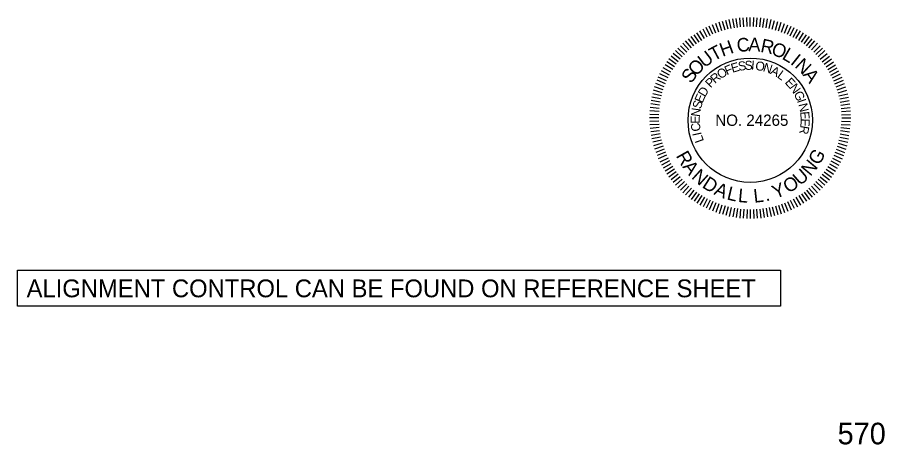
# Model space of a CAD drawing. Extents: x 1964850 to 1967424, y 1116563 to 1122204.
# Drawn here: x 1967080.5 to 1967421.9, y 1120475.5 to 1120643.6 of the extents above; entities that cross this region are included whole.
import ezdxf

# ---------------------------------------------------------------- set-up
doc = ezdxf.new("R2010")
doc.units = 0
for name, color, linetype in [('RD_DDB_Profile_Elev', 7, 'Continuous'), ('RD_Sketch1', 7, 'Continuous'), ('RD_TX_PEShield', 7, 'Continuous')]:
    doc.layers.add(name, color=color, linetype=linetype)

msp = doc.modelspace()

# ---------------------------------------------------------------- linework, layer by layer
at = {"layer": 'RD_Sketch1'}
msp.add_lwpolyline([(1967080.47, 1120544.18), (1967380.89, 1120544.18), (1967380.89, 1120529.92), (1967080.47, 1120529.92)], close=True, dxfattribs=at)
at = {"layer": 'RD_TX_PEShield'}
for p, q in [((1967369.01, 1120640.07), (1967369.01, 1120643.63)), ((1967369.01, 1120640.07), (1967369.01, 1120643.63)), ((1967354.35, 1120636.95), (1967352.9, 1120640.2)), ((1967354.35, 1120636.95), (1967352.9, 1120640.2)), ((1967355.53, 1120637.4), (1967354.19, 1120640.7)), ((1967355.53, 1120637.4), (1967354.19, 1120640.7)), ((1967356.7, 1120637.85), (1967355.48, 1120641.19)), ((1967356.7, 1120637.85), (1967355.48, 1120641.19)), ((1967357.87, 1120638.3), (1967356.77, 1120641.69)), ((1967357.87, 1120638.3), (1967356.77, 1120641.69)), ((1967359.09, 1120638.63), (1967358.11, 1120642.04)), ((1967359.09, 1120638.63), (1967358.11, 1120642.04)), ((1967360.3, 1120638.95), (1967359.44, 1120642.4)), ((1967360.3, 1120638.95), (1967359.44, 1120642.4)), ((1967361.52, 1120639.28), (1967360.78, 1120642.76)), ((1967361.52, 1120639.28), (1967360.78, 1120642.76)), ((1967362.76, 1120639.47), (1967362.14, 1120642.98)), ((1967362.76, 1120639.47), (1967362.14, 1120642.98)), ((1967364, 1120639.67), (1967363.51, 1120643.19)), ((1967364, 1120639.67), (1967363.51, 1120643.19)), ((1967365.24, 1120639.87), (1967364.87, 1120643.41)), ((1967365.24, 1120639.87), (1967364.87, 1120643.41)), ((1967366.5, 1120639.93), (1967366.25, 1120643.48)), ((1967366.5, 1120639.93), (1967366.25, 1120643.48)), ((1967367.76, 1120640), (1967367.63, 1120643.55)), ((1967367.76, 1120640), (1967367.63, 1120643.55)), ((1967370.27, 1120640), (1967370.39, 1120643.55)), ((1967370.27, 1120640), (1967370.39, 1120643.55)), ((1967371.52, 1120639.93), (1967371.77, 1120643.48)), ((1967371.52, 1120639.93), (1967371.77, 1120643.48)), ((1967372.78, 1120639.87), (1967373.15, 1120643.41)), ((1967372.78, 1120639.87), (1967373.15, 1120643.41)), ((1967374.02, 1120639.67), (1967374.52, 1120643.19)), ((1967374.02, 1120639.67), (1967374.52, 1120643.19)), ((1967375.26, 1120639.47), (1967375.88, 1120642.98)), ((1967375.26, 1120639.47), (1967375.88, 1120642.98)), ((1967376.51, 1120639.28), (1967377.25, 1120642.76)), ((1967376.51, 1120639.28), (1967377.25, 1120642.76)), ((1967376.51, 1120639.28), (1967377.25, 1120642.76)), ((1967377.72, 1120638.95), (1967378.58, 1120642.4)), ((1967377.72, 1120638.95), (1967378.58, 1120642.4)), ((1967377.72, 1120638.95), (1967378.58, 1120642.4)), ((1967378.93, 1120638.63), (1967379.91, 1120642.04)), ((1967378.93, 1120638.63), (1967379.91, 1120642.04)), ((1967378.93, 1120638.63), (1967379.91, 1120642.04)), ((1967380.15, 1120638.3), (1967381.25, 1120641.69)), ((1967380.15, 1120638.3), (1967381.25, 1120641.69)), ((1967380.15, 1120638.3), (1967381.25, 1120641.69)), ((1967381.32, 1120637.85), (1967382.54, 1120641.19)), ((1967381.32, 1120637.85), (1967382.54, 1120641.19)), ((1967381.32, 1120637.85), (1967382.54, 1120641.19)), ((1967382.5, 1120637.4), (1967383.83, 1120640.7)), ((1967382.5, 1120637.4), (1967383.83, 1120640.7)), ((1967382.5, 1120637.4), (1967383.83, 1120640.7)), ((1967383.67, 1120636.95), (1967385.12, 1120640.2)), ((1967383.67, 1120636.95), (1967385.12, 1120640.2)), ((1967383.67, 1120636.95), (1967385.12, 1120640.2)), ((1967348.88, 1120633.87), (1967346.89, 1120636.81)), ((1967348.88, 1120633.87), (1967346.89, 1120636.81)), ((1967349.93, 1120634.55), (1967348.05, 1120637.57)), ((1967349.93, 1120634.55), (1967348.05, 1120637.57)), ((1967350.99, 1120635.24), (1967349.21, 1120638.32)), ((1967350.99, 1120635.24), (1967349.21, 1120638.32)), ((1967352.11, 1120635.81), (1967350.44, 1120638.95)), ((1967352.11, 1120635.81), (1967350.44, 1120638.95)), ((1967353.23, 1120636.38), (1967351.67, 1120639.57)), ((1967353.23, 1120636.38), (1967351.67, 1120639.57)), ((1967384.79, 1120636.38), (1967386.35, 1120639.57)), ((1967384.79, 1120636.38), (1967386.35, 1120639.57)), ((1967384.79, 1120636.38), (1967386.35, 1120639.57)), ((1967385.91, 1120635.81), (1967387.58, 1120638.95)), ((1967385.91, 1120635.81), (1967387.58, 1120638.95)), ((1967385.91, 1120635.81), (1967387.58, 1120638.95)), ((1967387.03, 1120635.24), (1967388.81, 1120638.32)), ((1967387.03, 1120635.24), (1967388.81, 1120638.32)), ((1967387.03, 1120635.24), (1967388.81, 1120638.32)), ((1967388.09, 1120634.55), (1967389.97, 1120637.57)), ((1967388.09, 1120634.55), (1967389.97, 1120637.57)), ((1967388.09, 1120634.55), (1967389.97, 1120637.57)), ((1967389.14, 1120633.87), (1967391.13, 1120636.81)), ((1967389.14, 1120633.87), (1967391.13, 1120636.81)), ((1967389.14, 1120633.87), (1967391.13, 1120636.81)), ((1967344.89, 1120630.81), (1967342.51, 1120633.45)), ((1967344.89, 1120630.81), (1967342.51, 1120633.45)), ((1967345.87, 1120631.6), (1967343.59, 1120634.32)), ((1967345.87, 1120631.6), (1967343.59, 1120634.32)), ((1967346.85, 1120632.39), (1967344.66, 1120635.19)), ((1967346.85, 1120632.39), (1967344.66, 1120635.19)), ((1967347.82, 1120633.18), (1967345.73, 1120636.06)), ((1967347.82, 1120633.18), (1967345.73, 1120636.06)), ((1967390.2, 1120633.18), (1967392.29, 1120636.06)), ((1967390.2, 1120633.18), (1967392.29, 1120636.06)), ((1967390.2, 1120633.18), (1967392.29, 1120636.06)), ((1967391.18, 1120632.39), (1967393.37, 1120635.19)), ((1967391.18, 1120632.39), (1967393.37, 1120635.19)), ((1967391.18, 1120632.39), (1967393.37, 1120635.19)), ((1967392.15, 1120631.6), (1967394.44, 1120634.32)), ((1967392.15, 1120631.6), (1967394.44, 1120634.32)), ((1967392.15, 1120631.6), (1967394.44, 1120634.32)), ((1967393.13, 1120630.81), (1967395.51, 1120633.45)), ((1967393.13, 1120630.81), (1967395.51, 1120633.45)), ((1967393.13, 1120630.81), (1967395.51, 1120633.45)), ((1967342.22, 1120628.14), (1967339.58, 1120630.52)), ((1967342.22, 1120628.14), (1967339.58, 1120630.52)), ((1967343.11, 1120629.03), (1967340.56, 1120631.5)), ((1967343.11, 1120629.03), (1967340.56, 1120631.5)), ((1967344, 1120629.92), (1967341.53, 1120632.48)), ((1967344, 1120629.92), (1967341.53, 1120632.48)), ((1967394.02, 1120629.92), (1967396.49, 1120632.48)), ((1967394.02, 1120629.92), (1967396.49, 1120632.48)), ((1967394.02, 1120629.92), (1967396.49, 1120632.48)), ((1967394.91, 1120629.03), (1967397.47, 1120631.5)), ((1967394.91, 1120629.03), (1967397.47, 1120631.5)), ((1967394.91, 1120629.03), (1967397.47, 1120631.5)), ((1967395.8, 1120628.14), (1967398.44, 1120630.52)), ((1967395.8, 1120628.14), (1967398.44, 1120630.52)), ((1967395.8, 1120628.14), (1967398.44, 1120630.52)), ((1967339.85, 1120625.21), (1967336.97, 1120627.3)), ((1967339.85, 1120625.21), (1967336.97, 1120627.3)), ((1967340.64, 1120626.18), (1967337.84, 1120628.37)), ((1967340.64, 1120626.18), (1967337.84, 1120628.37)), ((1967341.43, 1120627.16), (1967338.71, 1120629.45)), ((1967341.43, 1120627.16), (1967338.71, 1120629.45)), ((1967396.59, 1120627.16), (1967399.31, 1120629.45)), ((1967396.59, 1120627.16), (1967399.31, 1120629.45)), ((1967396.59, 1120627.16), (1967399.31, 1120629.45)), ((1967397.38, 1120626.18), (1967400.18, 1120628.37)), ((1967397.38, 1120626.18), (1967400.18, 1120628.37)), ((1967397.38, 1120626.18), (1967400.18, 1120628.37)), ((1967398.17, 1120625.21), (1967401.05, 1120627.3)), ((1967398.17, 1120625.21), (1967401.05, 1120627.3)), ((1967398.17, 1120625.21), (1967401.05, 1120627.3)), ((1967337.8, 1120622.04), (1967334.71, 1120623.82)), ((1967337.8, 1120622.04), (1967334.71, 1120623.82)), ((1967338.48, 1120623.1), (1967335.47, 1120624.98)), ((1967338.48, 1120623.1), (1967335.47, 1120624.98)), ((1967339.17, 1120624.15), (1967336.22, 1120626.14)), ((1967339.17, 1120624.15), (1967336.22, 1120626.14)), ((1967398.86, 1120624.15), (1967401.81, 1120626.14)), ((1967398.86, 1120624.15), (1967401.81, 1120626.14)), ((1967398.86, 1120624.15), (1967401.81, 1120626.14)), ((1967399.54, 1120623.1), (1967402.56, 1120624.98)), ((1967399.54, 1120623.1), (1967402.56, 1120624.98)), ((1967399.54, 1120623.1), (1967402.56, 1120624.98)), ((1967400.23, 1120622.04), (1967403.31, 1120623.82)), ((1967400.23, 1120622.04), (1967403.31, 1120623.82)), ((1967400.23, 1120622.04), (1967403.31, 1120623.82)), ((1967336.08, 1120618.68), (1967332.83, 1120620.13)), ((1967336.08, 1120618.68), (1967332.83, 1120620.13)), ((1967336.65, 1120619.8), (1967333.46, 1120621.36)), ((1967336.65, 1120619.8), (1967333.46, 1120621.36)), ((1967337.22, 1120620.92), (1967334.09, 1120622.59)), ((1967337.22, 1120620.92), (1967334.09, 1120622.59)), ((1967400.8, 1120620.92), (1967403.94, 1120622.59)), ((1967400.8, 1120620.92), (1967403.94, 1120622.59)), ((1967400.8, 1120620.92), (1967403.94, 1120622.59)), ((1967401.37, 1120619.8), (1967404.57, 1120621.36)), ((1967401.37, 1120619.8), (1967404.57, 1120621.36)), ((1967401.37, 1120619.8), (1967404.57, 1120621.36)), ((1967401.94, 1120618.68), (1967405.19, 1120620.13)), ((1967401.94, 1120618.68), (1967405.19, 1120620.13)), ((1967401.94, 1120618.68), (1967405.19, 1120620.13)), ((1967335.18, 1120616.33), (1967331.84, 1120617.55)), ((1967335.18, 1120616.33), (1967331.84, 1120617.55)), ((1967335.63, 1120617.51), (1967332.34, 1120618.84)), ((1967335.63, 1120617.51), (1967332.34, 1120618.84)), ((1967402.39, 1120617.51), (1967405.69, 1120618.84)), ((1967402.39, 1120617.51), (1967405.69, 1120618.84)), ((1967402.39, 1120617.51), (1967405.69, 1120618.84)), ((1967402.84, 1120616.33), (1967406.18, 1120617.55)), ((1967402.84, 1120616.33), (1967406.18, 1120617.55)), ((1967402.84, 1120616.33), (1967406.18, 1120617.55)), ((1967334.08, 1120612.73), (1967330.63, 1120613.59)), ((1967334.08, 1120612.73), (1967330.63, 1120613.59)), ((1967334.41, 1120613.94), (1967330.99, 1120614.92)), ((1967334.41, 1120613.94), (1967330.99, 1120614.92)), ((1967334.73, 1120615.16), (1967331.35, 1120616.26)), ((1967334.73, 1120615.16), (1967331.35, 1120616.26)), ((1967403.29, 1120615.16), (1967406.68, 1120616.26)), ((1967403.29, 1120615.16), (1967406.68, 1120616.26)), ((1967403.29, 1120615.16), (1967406.68, 1120616.26)), ((1967403.62, 1120613.94), (1967407.04, 1120614.92)), ((1967403.62, 1120613.94), (1967407.04, 1120614.92)), ((1967403.62, 1120613.94), (1967407.04, 1120614.92)), ((1967403.94, 1120612.73), (1967407.39, 1120613.59)), ((1967403.94, 1120612.73), (1967407.39, 1120613.59)), ((1967403.94, 1120612.73), (1967407.39, 1120613.59)), ((1967333.36, 1120609.03), (1967329.84, 1120609.53)), ((1967333.36, 1120609.03), (1967329.84, 1120609.53)), ((1967333.56, 1120610.27), (1967330.06, 1120610.89)), ((1967333.56, 1120610.27), (1967330.06, 1120610.89)), ((1967333.75, 1120611.51), (1967330.27, 1120612.25)), ((1967333.75, 1120611.51), (1967330.27, 1120612.25)), ((1967404.27, 1120611.51), (1967407.75, 1120612.25)), ((1967404.27, 1120611.51), (1967407.75, 1120612.25)), ((1967404.27, 1120611.51), (1967407.75, 1120612.25)), ((1967404.47, 1120610.27), (1967407.97, 1120610.89)), ((1967404.47, 1120610.27), (1967407.97, 1120610.89)), ((1967404.47, 1120610.27), (1967407.97, 1120610.89)), ((1967404.66, 1120609.03), (1967408.18, 1120609.53)), ((1967404.66, 1120609.03), (1967408.18, 1120609.53)), ((1967404.66, 1120609.03), (1967408.18, 1120609.53)), ((1967333.1, 1120606.53), (1967329.55, 1120606.78)), ((1967333.1, 1120606.53), (1967329.55, 1120606.78)), ((1967333.16, 1120607.79), (1967329.62, 1120608.16)), ((1967333.16, 1120607.79), (1967329.62, 1120608.16)), ((1967404.86, 1120607.79), (1967408.4, 1120608.16)), ((1967404.86, 1120607.79), (1967408.4, 1120608.16)), ((1967404.86, 1120607.79), (1967408.4, 1120608.16)), ((1967404.93, 1120606.53), (1967408.47, 1120606.78)), ((1967404.93, 1120606.53), (1967408.47, 1120606.78)), ((1967404.93, 1120606.53), (1967408.47, 1120606.78)), ((1967332.97, 1120604.02), (1967329.41, 1120604.02)), ((1967332.97, 1120604.02), (1967329.41, 1120604.02)), ((1967333.03, 1120605.28), (1967329.48, 1120605.4)), ((1967333.03, 1120605.28), (1967329.48, 1120605.4)), ((1967333.03, 1120602.76), (1967329.48, 1120602.64)), ((1967333.03, 1120602.76), (1967329.48, 1120602.64)), ((1967404.92, 1120602.77), (1967408.47, 1120602.64)), ((1967404.92, 1120602.77), (1967408.47, 1120602.64)), ((1967404.99, 1120605.28), (1967408.54, 1120605.4)), ((1967404.99, 1120605.28), (1967408.54, 1120605.4)), ((1967404.99, 1120605.28), (1967408.54, 1120605.4)), ((1967405.06, 1120604.02), (1967408.62, 1120604.02)), ((1967405.06, 1120604.02), (1967408.62, 1120604.02)), ((1967405.06, 1120604.02), (1967408.62, 1120604.02)), ((1967333.1, 1120601.51), (1967329.55, 1120601.26)), ((1967333.1, 1120601.51), (1967329.55, 1120601.26)), ((1967333.16, 1120600.25), (1967329.62, 1120599.88)), ((1967333.16, 1120600.25), (1967329.62, 1120599.88)), ((1967404.66, 1120600.27), (1967408.18, 1120599.9)), ((1967404.66, 1120600.27), (1967408.18, 1120599.9)), ((1967404.79, 1120601.52), (1967408.33, 1120601.27)), ((1967404.79, 1120601.52), (1967408.33, 1120601.27)), ((1967333.36, 1120599.01), (1967329.84, 1120598.52)), ((1967333.36, 1120599.01), (1967329.84, 1120598.52)), ((1967333.56, 1120597.77), (1967330.06, 1120597.15)), ((1967333.56, 1120597.77), (1967330.06, 1120597.15)), ((1967333.75, 1120596.53), (1967330.27, 1120595.79)), ((1967333.75, 1120596.53), (1967330.27, 1120595.79)), ((1967404.27, 1120596.53), (1967407.75, 1120595.79)), ((1967404.27, 1120596.53), (1967407.75, 1120595.79)), ((1967404.4, 1120597.78), (1967407.9, 1120597.16)), ((1967404.4, 1120597.78), (1967407.9, 1120597.16)), ((1967404.53, 1120599.03), (1967408.04, 1120598.54)), ((1967404.53, 1120599.03), (1967408.04, 1120598.54)), ((1967334.08, 1120595.31), (1967330.63, 1120594.45)), ((1967334.08, 1120595.31), (1967330.63, 1120594.45)), ((1967334.41, 1120594.1), (1967330.99, 1120593.12)), ((1967334.41, 1120594.1), (1967330.99, 1120593.12)), ((1967334.73, 1120592.88), (1967331.35, 1120591.78)), ((1967403.29, 1120592.88), (1967406.68, 1120591.78)), ((1967403.29, 1120592.88), (1967406.68, 1120591.78)), ((1967403.62, 1120594.1), (1967407.04, 1120593.12)), ((1967403.62, 1120594.1), (1967407.04, 1120593.12)), ((1967403.94, 1120595.31), (1967407.39, 1120594.45)), ((1967403.94, 1120595.31), (1967407.39, 1120594.45)), ((1967335.18, 1120591.71), (1967331.84, 1120590.49)), ((1967335.18, 1120591.71), (1967331.84, 1120590.49)), ((1967335.63, 1120590.53), (1967332.34, 1120589.2)), ((1967335.63, 1120590.53), (1967332.34, 1120589.2)), ((1967336.08, 1120589.36), (1967332.83, 1120587.91)), ((1967336.08, 1120589.36), (1967332.83, 1120587.91)), ((1967401.94, 1120589.36), (1967405.19, 1120587.91)), ((1967401.94, 1120589.36), (1967405.19, 1120587.91)), ((1967402.39, 1120590.53), (1967405.69, 1120589.2)), ((1967402.39, 1120590.53), (1967405.69, 1120589.2)), ((1967402.84, 1120591.71), (1967406.18, 1120590.49)), ((1967402.84, 1120591.71), (1967406.18, 1120590.49)), ((1967336.65, 1120588.24), (1967333.46, 1120586.68)), ((1967336.65, 1120588.24), (1967333.46, 1120586.68)), ((1967337.22, 1120587.12), (1967334.09, 1120585.45)), ((1967337.22, 1120587.12), (1967334.09, 1120585.45)), ((1967337.8, 1120586), (1967334.71, 1120584.22)), ((1967337.8, 1120586), (1967334.71, 1120584.22)), ((1967400.23, 1120586), (1967403.31, 1120584.22)), ((1967400.23, 1120586), (1967403.31, 1120584.22)), ((1967400.8, 1120587.12), (1967403.94, 1120585.45)), ((1967400.8, 1120587.12), (1967403.94, 1120585.45)), ((1967401.37, 1120588.24), (1967404.57, 1120586.68)), ((1967401.37, 1120588.24), (1967404.57, 1120586.68)), ((1967338.48, 1120584.94), (1967335.47, 1120583.06)), ((1967338.48, 1120584.94), (1967335.47, 1120583.06)), ((1967339.17, 1120583.89), (1967336.22, 1120581.9)), ((1967339.17, 1120583.89), (1967336.22, 1120581.9)), ((1967339.85, 1120582.83), (1967336.97, 1120580.74)), ((1967339.85, 1120582.83), (1967336.97, 1120580.74)), ((1967398.17, 1120582.83), (1967401.05, 1120580.74)), ((1967398.17, 1120582.83), (1967401.05, 1120580.74)), ((1967398.86, 1120583.89), (1967401.81, 1120581.9)), ((1967398.86, 1120583.89), (1967401.81, 1120581.9)), ((1967399.54, 1120584.94), (1967402.56, 1120583.06)), ((1967399.54, 1120584.94), (1967402.56, 1120583.06)), ((1967340.64, 1120581.86), (1967337.84, 1120579.67)), ((1967340.64, 1120581.86), (1967337.84, 1120579.67)), ((1967341.43, 1120580.88), (1967338.71, 1120578.59)), ((1967341.43, 1120580.88), (1967338.71, 1120578.59)), ((1967342.22, 1120579.9), (1967339.58, 1120577.52)), ((1967342.22, 1120579.9), (1967339.58, 1120577.52)), ((1967343.11, 1120579.01), (1967340.56, 1120576.54)), ((1967343.11, 1120579.01), (1967340.56, 1120576.54)), ((1967394.91, 1120579.01), (1967397.47, 1120576.54)), ((1967394.91, 1120579.01), (1967397.47, 1120576.54)), ((1967395.8, 1120579.9), (1967398.44, 1120577.52)), ((1967395.8, 1120579.9), (1967398.44, 1120577.52)), ((1967396.59, 1120580.88), (1967399.31, 1120578.59)), ((1967396.59, 1120580.88), (1967399.31, 1120578.59)), ((1967397.38, 1120581.86), (1967400.18, 1120579.67)), ((1967397.38, 1120581.86), (1967400.18, 1120579.67)), ((1967344, 1120578.12), (1967341.53, 1120575.57)), ((1967344, 1120578.12), (1967341.53, 1120575.57)), ((1967344.89, 1120577.23), (1967342.51, 1120574.59)), ((1967344.89, 1120577.23), (1967342.51, 1120574.59)), ((1967345.87, 1120576.44), (1967343.59, 1120573.72)), ((1967345.87, 1120576.44), (1967343.59, 1120573.72)), ((1967346.85, 1120575.65), (1967344.66, 1120572.85)), ((1967346.85, 1120575.65), (1967344.66, 1120572.85)), ((1967391.18, 1120575.65), (1967393.37, 1120572.85)), ((1967391.18, 1120575.65), (1967393.37, 1120572.85)), ((1967392.15, 1120576.44), (1967394.44, 1120573.72)), ((1967392.15, 1120576.44), (1967394.44, 1120573.72)), ((1967393.13, 1120577.23), (1967395.51, 1120574.59)), ((1967394.02, 1120578.12), (1967396.49, 1120575.57)), ((1967394.02, 1120578.12), (1967396.49, 1120575.57)), ((1967347.82, 1120574.86), (1967345.73, 1120571.98)), ((1967347.82, 1120574.86), (1967345.73, 1120571.98)), ((1967348.88, 1120574.17), (1967346.89, 1120571.23)), ((1967348.88, 1120574.17), (1967346.89, 1120571.23)), ((1967349.93, 1120573.49), (1967348.05, 1120570.47)), ((1967349.93, 1120573.49), (1967348.05, 1120570.47)), ((1967350.99, 1120572.8), (1967349.21, 1120569.72)), ((1967350.99, 1120572.8), (1967349.21, 1120569.72)), ((1967352.11, 1120572.23), (1967350.44, 1120569.09)), ((1967352.11, 1120572.23), (1967350.44, 1120569.09)), ((1967385.91, 1120572.23), (1967387.58, 1120569.09)), ((1967385.91, 1120572.23), (1967387.58, 1120569.09)), ((1967387.03, 1120572.8), (1967388.81, 1120569.72)), ((1967387.03, 1120572.8), (1967388.81, 1120569.72)), ((1967388.09, 1120573.49), (1967389.97, 1120570.47)), ((1967388.09, 1120573.49), (1967389.97, 1120570.47)), ((1967389.14, 1120574.17), (1967391.13, 1120571.23)), ((1967389.14, 1120574.17), (1967391.13, 1120571.23)), ((1967390.2, 1120574.86), (1967392.29, 1120571.98)), ((1967390.2, 1120574.86), (1967392.29, 1120571.98)), ((1967353.23, 1120571.66), (1967351.67, 1120568.47)), ((1967353.23, 1120571.66), (1967351.67, 1120568.47)), ((1967354.35, 1120571.09), (1967352.9, 1120567.84)), ((1967354.35, 1120571.09), (1967352.9, 1120567.84)), ((1967355.53, 1120570.64), (1967354.19, 1120567.34)), ((1967355.53, 1120570.64), (1967354.19, 1120567.34)), ((1967356.7, 1120570.19), (1967355.48, 1120566.85)), ((1967356.7, 1120570.19), (1967355.48, 1120566.85)), ((1967357.87, 1120569.74), (1967356.77, 1120566.35)), ((1967357.87, 1120569.74), (1967356.77, 1120566.35)), ((1967359.09, 1120569.41), (1967358.11, 1120566)), ((1967359.09, 1120569.41), (1967358.11, 1120566)), ((1967360.3, 1120569.09), (1967359.44, 1120565.64)), ((1967360.3, 1120569.09), (1967359.44, 1120565.64)), ((1967361.52, 1120568.76), (1967360.78, 1120565.28)), ((1967361.52, 1120568.76), (1967360.78, 1120565.28)), ((1967362.76, 1120568.57), (1967362.14, 1120565.06)), ((1967362.76, 1120568.57), (1967362.14, 1120565.06)), ((1967375.26, 1120568.57), (1967375.88, 1120565.06)), ((1967375.26, 1120568.57), (1967375.88, 1120565.06)), ((1967376.51, 1120568.76), (1967377.25, 1120565.28)), ((1967376.51, 1120568.76), (1967377.25, 1120565.28)), ((1967377.72, 1120569.09), (1967378.58, 1120565.64)), ((1967377.72, 1120569.09), (1967378.58, 1120565.64)), ((1967378.93, 1120569.41), (1967379.91, 1120566)), ((1967378.93, 1120569.41), (1967379.91, 1120566)), ((1967380.15, 1120569.74), (1967381.25, 1120566.35)), ((1967380.15, 1120569.74), (1967381.25, 1120566.35)), ((1967381.32, 1120570.19), (1967382.54, 1120566.85)), ((1967381.32, 1120570.19), (1967382.54, 1120566.85)), ((1967382.5, 1120570.64), (1967383.83, 1120567.34)), ((1967382.5, 1120570.64), (1967383.83, 1120567.34)), ((1967383.67, 1120571.09), (1967385.12, 1120567.84)), ((1967383.67, 1120571.09), (1967385.12, 1120567.84)), ((1967384.79, 1120571.66), (1967386.35, 1120568.47)), ((1967384.79, 1120571.66), (1967386.35, 1120568.47)), ((1967364, 1120568.37), (1967363.51, 1120564.85)), ((1967364, 1120568.37), (1967363.51, 1120564.85)), ((1967365.24, 1120568.17), (1967364.87, 1120564.63)), ((1967365.24, 1120568.17), (1967364.87, 1120564.63)), ((1967366.5, 1120568.11), (1967366.25, 1120564.56)), ((1967366.5, 1120568.11), (1967366.25, 1120564.56)), ((1967367.76, 1120568.04), (1967367.63, 1120564.49)), ((1967367.76, 1120568.04), (1967367.63, 1120564.49)), ((1967369.01, 1120567.98), (1967369.01, 1120564.42)), ((1967369.01, 1120567.98), (1967369.01, 1120564.42)), ((1967370.27, 1120568.04), (1967370.39, 1120564.49)), ((1967370.27, 1120568.04), (1967370.39, 1120564.49)), ((1967371.52, 1120568.11), (1967371.77, 1120564.56)), ((1967371.52, 1120568.11), (1967371.77, 1120564.56)), ((1967372.78, 1120568.17), (1967373.15, 1120564.63)), ((1967372.78, 1120568.17), (1967373.15, 1120564.63)), ((1967374.02, 1120568.37), (1967374.52, 1120564.85)), ((1967374.02, 1120568.37), (1967374.52, 1120564.85))]:
    msp.add_line(p, q, dxfattribs=at)
msp.add_circle((1967369.01, 1120603.14), 24.48, dxfattribs=at)

# ---------------------------------------------------------------- texts
at = {"layer": 'RD_DDB_Profile_Elev'}
msp.add_text('570', height=8.5, dxfattribs=at).set_placement((1967403.42, 1120475.58))
at = {"layer": 'RD_Sketch1'}
msp.add_text('ALIGNMENT CONTROL CAN BE FOUND ON REFERENCE SHEET', height=7, dxfattribs=at).set_placement((1967084.12, 1120533.46))
at = {"layer": 'RD_TX_PEShield'}
for s, height, rotation, p in [('H', 5.34, 19.9102, (1967358.11, 1120628.06)), ('C', 5.34, 6.8832, (1967364.01, 1120629.88)), ('A', 5.34, 357.9448, (1967368.22, 1120630.33)), ('R', 5.34, 348.267, (1967372.8, 1120630.08)), ('O', 5.34, 339.3286, (1967376.94, 1120629.16)), ('U', 5.34, 37.7726, (1967350.99, 1120623.52)), ('T', 5.34, 28.0947, (1967354.67, 1120626.26)), ('L', 5.34, 329.6507, (1967381.2, 1120627.46)), ('O', 5.34, 47.4504, (1967347.82, 1120620.2)), ('S', 3.56, 1.79, (1967366.86, 1120622.93)), ('I', 3.56, 354.889, (1967369.26, 1120623.05)), ('I', 5.34, 321.4663, (1967384.54, 1120625.48)), ('N', 5.34, 317.0007, (1967386.23, 1120624.2)), ('S', 5.34, 54.9027, (1967345.79, 1120617.31)), ('O', 3.56, 31.7869, (1967357.26, 1120619.21)), ('F', 3.56, 23.0853, (1967359.82, 1120620.8)), ('E', 3.56, 16.1843, (1967362.01, 1120621.78)), ('S', 3.56, 8.6909, (1967364.5, 1120622.53)), ('O', 3.56, 350.4045, (1967370.81, 1120622.97)), ('N', 3.56, 341.7029, (1967373.79, 1120622.47)), ('A', 3.56, 333.0013, (1967376.66, 1120621.52)), ('P', 3.56, 46.7912, (1967353.5, 1120615.62)), ('R', 3.56, 39.8902, (1967355.11, 1120617.39)), ('L', 3.56, 324.2997, (1967379.35, 1120620.15)), ('E', 3.56, 313.2251, (1967382.43, 1120617.85)), ('A', 5.34, 307.3229, (1967389.53, 1120621)), ('N', 3.56, 305.7317, (1967384.23, 1120615.98)), ('E', 3.56, 66.5674, (1967350.19, 1120609.63)), ('D', 3.56, 59.074, (1967351.2, 1120612.03)), ('G', 3.56, 297.0301, (1967386, 1120613.53)), ('S', 3.56, 73.4683, (1967349.55, 1120607.32)), ('I', 3.56, 288.3285, (1967387.37, 1120610.84)), ('N', 3.56, 283.8441, (1967387.92, 1120609.38)), ('N', 3.56, 82.17, (1967349.14, 1120604.33)), ('E', 3.56, 275.1424, (1967388.64, 1120606.45)), ('E', 3.56, 89.6633, (1967349.16, 1120601.73)), ('E', 3.56, 267.6491, (1967388.9, 1120603.86)), ('C', 3.56, 97.7667, (1967349.55, 1120598.94)), ('R', 3.56, 260.1557, (1967388.83, 1120601.26)), ('I', 3.56, 102.2511, (1967349.94, 1120597.44)), ('L', 3.56, 109.7445, (1967350.85, 1120595)), ('R', 5.34, 299.1493, (1967339.61, 1120589.17)), ('G', 5.34, 60.1113, (1967396.12, 1120585.12)), ('A', 5.34, 308.0877, (1967342.14, 1120584.77)), ('N', 5.34, 50.4335, (1967392.71, 1120580.82)), ('N', 5.34, 317.7655, (1967345.61, 1120580.51)), ('U', 5.34, 40.7556, (1967388.62, 1120577.15)), ('D', 5.34, 327.4433, (1967349.75, 1120576.9)), ('Y', 5.34, 21.4, (1967378.89, 1120572.12)), ('O', 5.34, 31.0778, (1967383.97, 1120574.23)), ('A', 5.34, 337.1212, (1967354.43, 1120574.04)), ('L', 5.34, 346.799, (1967359.53, 1120572)), ('L', 5.34, 354.9835, (1967364.06, 1120570.97)), ('L', 5.34, 6.5171, (1967370.59, 1120570.63)), ('.', 5.34, 14.7016, (1967375.21, 1120571.18))]:
    msp.add_text(s, height=height, rotation=rotation, dxfattribs=at).set_placement(p)
msp.add_text('NO. 24265', height=4.45, dxfattribs=at).set_placement((1967355.26, 1120600.92))

doc.saveas('drawing.dxf')
